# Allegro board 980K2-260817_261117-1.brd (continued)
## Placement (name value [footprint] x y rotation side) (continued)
NOREF#1107  -  []  178.97 271.91 90 top
NOREF#1108  -  []  211.21 294.89 90 top
NOREF#1109  -  []  279.22 250.88 90 top
NOREF#1110  -  []  256.83 227.03 0 top
NOREF#1111  -  []  271.19 228.49 0 top
NOREF#1112  -  []  171.05 289.49 0 top
NOREF#1113  -  []  237.92 250.01 0 top
NOREF#1114  -  []  158.11 172.1 0 top
NOREF#1115  -  []  226.16 272.17 90 top
NOREF#1116  -  []  244.44 232.28 90 top
NOREF#1117  -  []  214.38 264.09 0 top
NOREF#1118  -  []  93.68 156.59 0 top
NOREF#1119  -  []  149.84 224.11 0 top
NOREF#1120  -  []  262.87 273.02 0 top
NOREF#1121  -  []  149.72 221.62 0 top
NOREF#1122  -  []  144.16 256.43 90 top
NOREF#1123  -  []  275.17 272.17 0 top
NOREF#1124  -  []  146.16 193.35 0 top
NOREF#1125  -  []  224.16 251.6 90 top
NOREF#1126  -  []  273.94 256.75 0 top
NOREF#1127  -  []  277.74 166.36 90 top
NOREF#1128  -  []  214.43 232.23 0 top
NOREF#1129  -  []  208.54 267.5 90 top
NOREF#1130  -  []  196.61 233.37 90 top
NOREF#1131  -  []  283.84 270.87 90 top
NOREF#1132  -  []  135.82 266.44 0 top
NOREF#1133  -  []  218.83 292.23 0 top
NOREF#1134  -  []  119.48 396.29 0 top
NOREF#1135  -  []  237.74 226.35 90 top
NOREF#1136  -  []  273.27 198.18 0 top
NOREF#1137  -  []  152.46 247.68 90 top
NOREF#1138  -  []  243.97 270.55 90 top
NOREF#1139  -  []  148.35 223.79 90 top
NOREF#1140  -  []  262.03 229.03 90 top
NOREF#1141  -  []  157.5 245.31 90 top
NOREF#1142  -  []  193.6 216.55 0 top
NOREF#1143  -  []  193.39 193.03 90 top
NOREF#1144  -  []  236.33 167.9 90 top
NOREF#1145  -  []  269.84 279.54 90 top
NOREF#1146  -  []  248.54 202.09 0 top
NOREF#1147  -  []  186.01 250.88 90 top
NOREF#1148  -  []  163.84 264.78 90 top
NOREF#1149  -  []  272.13 284.66 0 top
NOREF#1150  -  []  276.7 257.85 90 top
NOREF#1151  -  []  159.27 210.87 90 top
NOREF#1152  -  []  89.76 164.74 90 top
NOREF#1153  -  []  239.4 213.09 90 top
NOREF#1154  -  []  129.49 266.31 0 top
NOREF#1155  -  []  279.27 205.58 0 top
NOREF#1156  -  []  185.42 214.72 90 top
NOREF#1157  -  []  147.77 248.11 90 top
NOREF#1158  -  []  237.71 233.69 0 top
NOREF#1159  -  []  211.25 244.35 0 top
NOREF#1160  -  []  279.27 268.62 0 top
NOREF#1161  -  []  135.15 263.21 0 top
NOREF#1162  -  []  225.41 286.99 90 top
NOREF#1163  -  []  187.01 458.49 0 top
NOREF#1164  -  []  157.71 173.69 90 top
NOREF#1165  -  []  277.71 233.69 0 top
NOREF#1166  -  []  243.97 274.54 0 top
NOREF#1167  -  []  164.95 267.27 90 top
NOREF#1168  -  []  195.05 278.82 0 top
NOREF#1169  -  []  162.57 291.95 0 top
NOREF#1170  -  []  239.4 274.54 0 top
NOREF#1171  -  []  206.32 209.17 0 top
NOREF#1172  -  []  203.84 214.21 0 top
NOREF#1173  -  []  150.88 168.6 90 top
NOREF#1174  -  []  233.27 198.18 0 top
NOREF#1175  -  []  171.25 244.35 0 top
NOREF#1176  -  []  240.23 176.17 90 top
NOREF#1177  -  []  0 382.27 0 top
NOREF#1178  -  []  189.12 251.6 90 top
NOREF#1179  -  []  203.97 208.95 0 top
NOREF#1180  -  []  266.43 222.5 90 top
NOREF#1181  -  []  243.4 296.38 0 top
NOREF#1182  -  []  266.28 253.03 90 top
NOREF#1183  -  []  141.43 285.38 90 top
NOREF#1184  -  []  236.7 257.85 90 top
NOREF#1185  -  []  230.97 190.88 90 top
NOREF#1186  -  []  228.32 242.05 0 top
NOREF#1187  -  []  279.4 262.09 0 top
NOREF#1188  -  []  274.39 282.02 90 top
NOREF#1189  -  []  137.28 272.5 90 top
NOREF#1190  -  []  156.02 247.68 0 top
NOREF#1191  -  []  190.97 190.88 90 top
NOREF#1192  -  []  289.52 207.27 90 top
NOREF#1193  -  []  256.98 265.11 90 top
NOREF#1194  -  []  317.15 392.33 90 top
NOREF#1195  -  []  232.13 280.09 0 top
NOREF#1196  -  []  230.77 279.22 90 top
NOREF#1197  -  []  119.46 18.69 90 top
NOREF#1198  -  []  138.95 264.09 0 top
NOREF#1199  -  []  256.63 232.23 0 top
NOREF#1200  -  []  237.37 191.6 90 top
NOREF#1201  -  []  231.19 283.92 0 top
NOREF#1202  -  []  235.05 218.82 0 top
NOREF#1203  -  []  187.43 284.11 0 top
NOREF#1204  -  []  215.02 208.14 90 top
NOREF#1205  -  []  225 456.29 0 top
NOREF#1206  -  []  239.4 204.45 90 top
NOREF#1207  -  []  212.87 227.4 90 top
NOREF#1208  -  []  140.83 265.79 90 top
NOREF#1209  -  []  271.91 256.43 90 top
NOREF#1210  -  []  152.66 226.35 90 top
NOREF#1211  -  []  197.03 178.07 0 top
NOREF#1212  -  []  193.18 211.85 90 top
NOREF#1213  -  []  168.42 261.77 0 top
NOREF#1214  -  []  243.84 214.21 0 top
NOREF#1215  -  []  249.05 232.28 0 top
NOREF#1216  -  []  203.84 205.58 0 top
NOREF#1217  -  []  266.01 184.91 90 top
NOREF#1218  -  []  283.84 271.67 0 top
NOREF#1219  -  []  156.02 192.78 0 top
NOREF#1220  -  []  230.56 197.6 0 top
NOREF#1221  -  []  220.43 284.38 90 top
NOREF#1222  -  []  122.57 231.95 0 top
NOREF#1223  -  []  236.54 227 0 top
NOREF#1224  -  []  275.15 236.17 90 top
NOREF#1225  -  []  210.92 291.95 90 top
NOREF#1226  -  []  203.97 272 0 top
NOREF#1227  -  []  148.32 245.63 0 top
NOREF#1228  -  []  189.84 224.11 0 top
NOREF#1229  -  []  270.56 197.6 0 top
NOREF#1230  -  []  204.64 241.15 90 top
NOREF#1231  -  []  147.03 171.4 0 top
NOREF#1232  -  []  220.83 201.22 90 top
NOREF#1233  -  []  273.27 253.35 0 top
NOREF#1234  -  []  228.32 253.35 0 top
NOREF#1235  -  []  248.54 207.5 90 top
NOREF#1236  -  []  186.16 286.14 90 top
NOREF#1237  -  []  239.27 261.77 0 top
NOREF#1238  -  []  159.27 271.67 0 top
NOREF#1239  -  []  147.77 181.47 0 top
NOREF#1240  -  []  208.94 281.73 0 top
NOREF#1241  -  []  267.05 269.24 0 top
NOREF#1242  -  []  206.32 202.32 0 top
NOREF#1243  -  []  204.95 210.32 90 top
NOREF#1244  -  []  229.12 256.43 90 top
NOREF#1245  -  []  212.55 190.49 90 top
NOREF#1246  -  []  266.43 282.49 90 top
NOREF#1247  -  []  249.52 200.42 90 top
NOREF#1248  -  []  180.95 266.12 90 top
NOREF#1249  -  []  169.52 270.32 90 top
NOREF#1250  -  []  277.5 185.31 90 top
NOREF#1251  -  []  276.57 185.63 0 top
NOREF#1252  -  []  152.13 280.09 0 top
NOREF#1253  -  []  273.27 258.18 0 top
NOREF#1254  -  []  154.33 267.37 90 top
NOREF#1255  -  []  245.38 286.23 0 top
NOREF#1256  -  []  276.57 193.35 0 top
NOREF#1257  -  []  145.42 286.99 90 top
NOREF#1258  -  []  286.32 212.22 0 top
NOREF#1259  -  []  275.49 168.7 90 top
NOREF#1260  -  []  178.83 292.23 0 top
NOREF#1261  -  []  293.99 17.15 0 top
NOREF#1262  -  []  153.39 257.85 90 top
NOREF#1263  -  []  188.95 206.89 0 top
NOREF#1264  -  []  279.27 267.82 90 top
NOREF#1265  -  []  176.72 18.69 0 top
NOREF#1266  -  []  267.3 226.19 0 top
NOREF#1267  -  []  239.24 244.35 0 top
NOREF#1268  -  []  199.4 214.54 0 top
NOREF#1269  -  []  236.52 225.69 0 top
NOREF#1270  -  []  223.49 197.85 90 top
NOREF#1271  -  []  181.85 232.5 0 top
NOREF#1272  -  []  267.43 278.27 90 top
NOREF#1273  -  []  161.75 272.22 0 top
NOREF#1274  -  []  277.04 244.35 0 top
NOREF#1275  -  []  231.79 251.93 0 top
NOREF#1276  -  []  147.43 218.27 0 top
NOREF#1277  -  []  154.63 283.79 90 top
NOREF#1278  -  []  226.43 282.49 90 top
NOREF#1279  -  []  271.79 191.93 0 top
NOREF#1280  -  []  187.43 278.27 0 top
NOREF#1281  -  []  241.75 266.13 0 top
NOREF#1282  -  []  148.95 206.89 0 top
NOREF#1283  -  []  213.45 184.35 0 top
NOREF#1284  -  []  256.55 280.49 0 top
NOREF#1285  -  []  144.71 252.5 90 top
NOREF#1286  -  []  272.25 272.17 0 top
NOREF#1287  -  []  201.75 209.17 0 top
NOREF#1288  -  []  230.6 233.69 0 top
NOREF#1289  -  []  242.85 297.22 0 top
NOREF#1290  -  []  208.54 205.9 0 top
NOREF#1291  -  []  203.84 260.97 90 top
NOREF#1292  -  []  258.35 211.84 0 top
NOREF#1293  -  []  278.11 232.1 0 top
NOREF#1294  -  []  218.85 181.15 90 top
NOREF#1295  -  []  232.25 212.18 0 top
NOREF#1296  -  []  143.36 258.18 0 top
NOREF#1297  -  []  199.72 283.79 90 top
NOREF#1298  -  []  187 83.81 0 top
NOREF#1299  -  []  232.13 224.66 0 top
NOREF#1300  -  []  324.88 21.69 90 top
NOREF#1301  -  []  231.11 253.35 0 top
NOREF#1302  -  []  203.84 271.67 0 top
NOREF#1303  -  []  275.05 278.82 0 top
NOREF#1304  -  []  140.83 208.59 90 top
NOREF#1305  -  []  163.84 204.78 90 top
NOREF#1306  -  []  263.49 253.03 90 top
NOREF#1307  -  []  151.19 218.07 0 top
NOREF#1308  -  []  225.09 197.49 90 top
NOREF#1309  -  []  228.78 222.65 0 top
NOREF#1310  -  []  139.73 178.35 0 top
NOREF#1311  -  []  230.77 213.37 90 top
NOREF#1312  -  []  152.25 278.02 90 top
NOREF#1313  -  []  208.54 265.9 0 top
NOREF#1314  -  []  229.72 221.62 0 top
NOREF#1315  -  []  144.04 245.96 0 top
NOREF#1316  -  []  283.84 213.41 90 top
NOREF#1317  -  []  214.04 210.63 90 top
NOREF#1318  -  []  250.89 269.17 0 top
NOREF#1319  -  []  277.59 175.77 0 top
NOREF#1320  -  []  220.63 392.33 90 top
NOREF#1321  -  []  255.84 262.57 90 top
NOREF#1322  -  []  154.07 256.43 90 top
NOREF#1323  -  []  179.08 263.76 0 top
NOREF#1324  -  []  218.95 201.55 0 top
NOREF#1325  -  []  190.41 168.7 90 top
NOREF#1326  -  []  248.54 262.09 0 top
NOREF#1327  -  []  273.83 232.21 90 top
NOREF#1328  -  []  268.99 256.75 0 top
NOREF#1329  -  []  191.11 198.18 0 top
NOREF#1330  -  []  276.45 187.71 0 top
NOREF#1331  -  []  157.92 247.68 90 top
NOREF#1332  -  []  185.09 197.49 90 top
NOREF#1333  -  []  268.32 182.05 0 top
NOREF#1334  -  []  171.05 229.49 0 top
NOREF#1335  -  []  258.35 267.01 0 top
NOREF#1336  -  []  128.48 456.29 0 top
NOREF#1337  -  []  203.97 204.45 90 top
NOREF#1338  -  []  235.17 276.75 0 top
NOREF#1339  -  []  279.27 265.58 0 top
NOREF#1340  -  []  279.65 272.56 0 top
NOREF#1341  -  []  149.84 273.7 0 top
NOREF#1342  -  []  196.8 225.06 90 top
NOREF#1343  -  []  226.83 191.93 0 top
NOREF#1344  -  []  233.6 276.55 0 top
NOREF#1345  -  []  129.49 220.89 0 top
NOREF#1346  -  []  187.99 238.35 0 top
NOREF#1347  -  []  221.85 306.46 0 top
NOREF#1348  -  []  186.16 272.17 90 top
NOREF#1349  -  []  294.09 204.23 90 top
NOREF#1350  -  []  186.01 190.88 90 top
NOREF#1351  -  []  244.95 264.23 90 top
NOREF#1352  -  []  196.02 252.78 0 top
NOREF#1353  -  []  193.95 256.75 0 top
NOREF#1354  -  []  147.77 192.78 0 top
NOREF#1355  -  []  204.61 294.89 90 top
NOREF#1356  -  []  95.33 20.69 90 top
NOREF#1357  -  []  148.99 251.93 0 top
NOREF#1358  -  []  145.42 214.72 90 top
NOREF#1359  -  []  176.83 227.03 0 top
NOREF#1360  -  []  191.73 232.54 0 top
NOREF#1361  -  []  187.3 220.35 0 top
NOREF#1362  -  []  187.43 224.11 0 top
NOREF#1363  -  []  267.43 284.11 90 top
NOREF#1364  -  []  93.68 136.27 0 top
NOREF#1365  -  []  155.17 212.18 90 top
NOREF#1366  -  []  138.97 271.91 90 top
NOREF#1367  -  []  229.12 251.6 90 top
NOREF#1368  -  []  248.54 260.64 90 top
NOREF#1369  -  []  199.27 260.97 90 top
NOREF#1370  -  []  276.84 227.33 0 top
NOREF#1371  -  []  245.04 293.3 90 top
NOREF#1372  -  []  240.13 396.29 0 top
NOREF#1373  -  []  283.97 208.95 0 top
NOREF#1374  -  []  193.18 184.35 0 top
NOREF#1375  -  []  186.83 196.75 0 top
NOREF#1376  -  []  239.27 270.87 90 top
NOREF#1377  -  []  135.02 208.14 90 top
NOREF#1378  -  []  274.39 226.59 90 top
NOREF#1379  -  []  187.99 178.35 0 top
NOREF#1380  -  []  181.85 292.49 0 top
NOREF#1381  -  []  235.68 233.69 90 top
NOREF#1382  -  []  273.94 251.93 0 top
NOREF#1383  -  []  193.39 257.85 90 top
NOREF#1384  -  []  186.83 191.93 0 top
NOREF#1385  -  []  146.96 251.6 90 top
NOREF#1386  -  []  236.57 185.63 0 top
NOREF#1387  -  []  183.36 253.35 0 top
NOREF#1388  -  []  204.95 200.42 90 top
NOREF#1389  -  []  239.27 207.82 90 top
NOREF#1390  -  []  191.24 197.85 90 top
NOREF#1391  -  []  283.84 208.62 0 top
NOREF#1392  -  []  212.55 250.49 90 top
NOREF#1393  -  []  231.11 193.35 0 top
NOREF#1394  -  []  157.5 185.31 90 top
NOREF#1395  -  []  135.11 261.22 90 top
NOREF#1396  -  []  190.98 184.35 0 top
NOREF#1397  -  []  155.17 281.32 0 top
NOREF#1398  -  []  157.71 233.69 90 top
NOREF#1399  -  []  192.13 220.09 0 top
NOREF#1400  -  []  233.39 257.85 90 top
NOREF#1401  -  []  267.99 178.35 0 top
NOREF#1402  -  []  209.52 272.86 90 top
NOREF#1403  -  []  186.7 283.04 90 top
NOREF#1404  -  []  289.52 200.42 90 top
NOREF#1405  -  []  178.35 271.84 0 top
NOREF#1406  -  []  254.38 204.09 0 top
NOREF#1407  -  []  233.18 271.85 90 top
NOREF#1408  -  []  140.83 205.79 90 top
NOREF#1409  -  []  226.01 250.88 90 top
NOREF#1410  -  []  197.5 185.31 90 top
NOREF#1411  -  []  225.42 274.72 90 top
NOREF#1412  -  []  123.92 289.94 0 top
NOREF#1413  -  []  273.18 222.26 90 top
NOREF#1414  -  []  151.19 228.49 0 top
NOREF#1415  -  []  236.1 280.99 90 top
NOREF#1416  -  []  139.73 178.35 0 top
NOREF#1417  -  []  272.51 235.77 0 top
NOREF#1418  -  []  151.11 200.17 90 top
NOREF#1419  -  []  251.25 184.35 0 top
NOREF#1420  -  []  157.92 190.01 0 top
NOREF#1421  -  []  155.17 221.32 90 top
NOREF#1422  -  []  148.35 283.79 90 top
NOREF#1423  -  []  248.42 207.82 90 top
NOREF#1424  -  []  169.52 260.42 90 top
NOREF#1425  -  []  266.16 258.18 0 top
NOREF#1426  -  []  159.22 190.88 90 top
NOREF#1427  -  []  151.18 179.15 0 top
NOREF#1428  -  []  185.09 257.49 90 top
NOREF#1429  -  []  192.11 231.4 0 top
NOREF#1430  -  []  124.61 294.89 90 top
NOREF#1431  -  []  273.18 277.69 90 top
NOREF#1432  -  []  262.81 252.78 0 top
NOREF#1433  -  []  164.95 204.23 90 top
NOREF#1434  -  []  203.97 212 0 top
NOREF#1435  -  []  133.1 237.5 0 top
NOREF#1436  -  []  227.8 205.39 90 top
NOREF#1437  -  []  140.95 206.12 90 top
NOREF#1438  -  []  216 456.29 90 top
NOREF#1439  -  []  114.62 458.49 0 top
NOREF#1440  -  []  187.45 269.24 0 top
NOREF#1441  -  []  198.11 172.1 0 top
NOREF#1442  -  []  236.02 257.6 0 top
NOREF#1443  -  []  231.98 286.59 90 top
NOREF#1444  -  []  288.54 262.09 0 top
NOREF#1445  -  []  152.51 235.77 0 top
NOREF#1446  -  []  140.95 201.55 90 top
NOREF#1447  -  []  232.51 175.77 0 top
NOREF#1448  -  []  230.56 257.6 0 top
NOREF#1449  -  []  143.49 257.85 90 top
NOREF#1450  -  []  169.05 232.28 0 top
NOREF#1451  -  []  152.63 173.69 90 top
NOREF#1452  -  []  148.99 240.62 0 top
NOREF#1453  -  []  276.33 227.9 90 top
NOREF#1454  -  []  139.08 205.79 0 top
NOREF#1455  -  []  239.4 200.64 90 top
NOREF#1456  -  []  149.72 275.77 0 top
NOREF#1457  -  []  166.32 269.17 0 top
NOREF#1458  -  []  254.43 292.23 0 top
NOREF#1459  -  []  188.78 184.35 0 top
NOREF#1460  -  []  268.95 206.89 0 top
NOREF#1461  -  []  226.01 184.91 90 top
NOREF#1462  -  []  276.84 167.33 0 top
NOREF#1463  -  []  236.1 211.85 90 top
NOREF#1464  -  []  163.84 265.58 0 top
NOREF#1465  -  []  242.44 292.28 0 top
NOREF#1466  -  []  227.45 209.24 0 top
NOREF#1467  -  []  213.36 201.22 0 top
NOREF#1468  -  []  259.73 178.35 0 top
NOREF#1469  -  []  125.04 233.3 90 top
NOREF#1470  -  []  143.49 247.06 90 top
NOREF#1471  -  []  151.98 220.75 90 top
NOREF#1472  -  []  288.42 200.97 90 top
NOREF#1473  -  []  277.92 250.01 0 top
NOREF#1474  -  []  180.95 264.09 90 top
NOREF#1475  -  []  269.55 248.99 90 top
NOREF#1476  -  []  222.81 197.6 0 top
NOREF#1477  -  []  173.45 244.35 0 top
NOREF#1478  -  []  279.4 202.09 0 top
NOREF#1479  -  []  193.6 276.55 0 top
NOREF#1480  -  []  239.22 239.57 90 top
NOREF#1481  -  []  281.75 262.32 0 top
NOREF#1482  -  []  268.81 255.7 90 top
NOREF#1483  -  []  211.05 289.49 0 top
NOREF#1484  -  []  229.12 180.3 90 top
NOREF#1485  -  []  262.81 192.78 0 top
NOREF#1486  -  []  228.78 184.35 0 top
NOREF#1487  -  []  157.37 196.43 90 top
NOREF#1488  -  []  161.41 227.9 90 top
NOREF#1489  -  []  255.84 202.57 90 top
NOREF#1490  -  []  197.71 232.86 0 top
NOREF#1491  -  []  223.36 247.38 0 top
NOREF#1492  -  []  276.1 220.99 90 top
NOREF#1493  -  []  235.05 223.39 0 top
NOREF#1494  -  []  143.49 253.03 90 top
NOREF#1495  -  []  145.42 273.02 90 top
NOREF#1496  -  []  156.79 171.3 0 top
NOREF#1497  -  []  288.42 204.78 90 top
NOREF#1498  -  []  214.07 210.89 90 top
NOREF#1499  -  []  246.32 274.76 0 top
NOREF#1500  -  []  188.44 253.03 90 top
NOREF#1501  -  []  183.49 247.06 90 top
NOREF#1502  -  []  264.26 456.29 90 top
NOREF#1503  -  []  157.28 264.37 0 top
NOREF#1504  -  []  276.8 285.06 90 top
NOREF#1505  -  []  156.57 198.18 0 top
NOREF#1506  -  []  271.46 227 0 top
NOREF#1507  -  []  151.19 223.92 0 top
NOREF#1508  -  []  275.49 228.7 90 top
NOREF#1509  -  []  230.97 255.7 90 top
NOREF#1510  -  []  270.48 175.77 0 top
NOREF#1511  -  []  164.04 237.5 90 top
NOREF#1512  -  []  225.61 257.6 0 top
NOREF#1513  -  []  169.05 292.28 0 top
NOREF#1514  -  []  155.17 276.75 0 top
NOREF#1515  -  []  244.61 234.24 90 top
NOREF#1516  -  []  203.84 264.78 90 top
NOREF#1517  -  []  191.53 233.37 90 top
NOREF#1518  -  []  214.09 207.27 90 top
NOREF#1519  -  []  209.52 270.32 90 top
NOREF#1520  -  []  172.64 264.47 0 top
NOREF#1521  -  []  268.78 244.35 0 top
NOREF#1522  -  []  182.81 192.78 0 top
NOREF#1523  -  []  263.36 258.18 0 top
NOREF#1524  -  []  195.17 212.18 90 top
NOREF#1525  -  []  192.72 252.78 0 top
NOREF#1526  -  []  95.35 456.29 90 top
NOREF#1527  -  []  190.56 257.6 0 top
NOREF#1528  -  []  163.84 200.97 90 top
NOREF#1529  -  []  239.4 207.5 90 top
NOREF#1530  -  []  260.83 201.22 90 top
NOREF#1531  -  []  272.51 175.77 0 top
NOREF#1532  -  []  159.06 238.07 0 top
NOREF#1533  -  []  231.24 197.85 90 top
NOREF#1534  -  []  277.92 190.01 0 top
NOREF#1535  -  []  117.23 452.29 90 top
NOREF#1536  -  []  163.97 272 0 top
NOREF#1537  -  []  132.64 204.47 0 top
NOREF#1538  -  []  283.84 267.82 90 top
NOREF#1539  -  []  228.44 253.03 90 top
NOREF#1540  -  []  272.72 197.6 0 top
NOREF#1541  -  []  196.79 231.3 0 top
NOREF#1542  -  []  277.37 191.6 90 top
NOREF#1543  -  []  225.09 257.49 90 top
NOREF#1544  -  []  318.12 17.15 90 top
NOREF#1545  -  []  227.3 220.35 0 top
NOREF#1546  -  []  231.19 228.49 0 top
NOREF#1547  -  []  180.83 261.22 90 top
NOREF#1548  -  []  197.74 166.36 90 top
NOREF#1549  -  []  139.08 208.59 0 top
NOREF#1550  -  []  156.7 181.72 90 top
NOREF#1551  -  []  158.04 228.3 0 top
NOREF#1552  -  []  147.8 204.99 90 top
NOREF#1553  -  []  269.86 17.15 0 top
NOREF#1554  -  []  268.32 185.63 90 top
NOREF#1555  -  []  233.18 217.69 90 top
NOREF#1556  -  []  272.25 222.59 90 top
NOREF#1557  -  []  265.41 273.02 90 top
NOREF#1558  -  []  209.17 231.95 0 top
NOREF#1559  -  []  272.25 278.02 90 top
NOREF#1560  -  []  131.22 234.24 90 top
NOREF#1561  -  []  272.66 166.36 90 top
NOREF#1562  -  []  118.64 291.4 0 top
NOREF#1563  -  []  177.29 187.78 0 top
NOREF#1564  -  []  210.89 269.17 0 top
NOREF#1565  -  []  189.55 248.99 90 top
NOREF#1566  -  []  239.22 255.7 90 top
NOREF#1567  -  []  289.52 212.86 90 top
NOREF#1568  -  []  266.01 244.91 90 top
NOREF#1569  -  []  266.96 256.43 90 top
NOREF#1570  -  []  146.88 283.95 0 top
NOREF#1571  -  []  194.78 176.5 90 top
NOREF#1572  -  []  263.36 198.18 0 top
NOREF#1573  -  []  149.84 279.54 0 top
NOREF#1574  -  []  171.22 234.24 90 top
NOREF#1575  -  []  205.04 293.3 90 top
NOREF#1576  -  []  239.22 190.88 90 top
NOREF#1577  -  []  158.91 172.21 90 top
NOREF#1578  -  []  152.25 282.59 90 top
NOREF#1579  -  []  260.59 184.98 90 top
NOREF#1580  -  []  153.76 190.88 90 top
NOREF#1581  -  []  217.25 176.5 90 top
NOREF#1582  -  []  221.03 267.69 90 top
NOREF#1583  -  []  279.4 265.9 0 top
NOREF#1584  -  []  85.84 137.3 0 top
NOREF#1585  -  []  281.75 206.13 0 top
NOREF#1586  -  []  239.27 214.21 0 top
NOREF#1587  -  []  254.07 270.89 90 top
NOREF#1588  -  []  163.92 229.94 0 top
NOREF#1589  -  []  228.99 196.75 0 top
NOREF#1590  -  []  134.51 263.76 0 top
NOREF#1591  -  []  199.4 265.9 0 top
NOREF#1592  -  []  152.25 218.02 0 top
NOREF#1593  -  []  209.52 267.27 90 top
NOREF#1594  -  []  190.77 219.22 90 top
NOREF#1595  -  []  142.03 229.03 90 top
NOREF#1596  -  []  271.19 223.92 0 top
NOREF#1597  -  []  154.39 226.59 90 top
NOREF#1598  -  []  148.44 241.72 90 top
NOREF#1599  -  []  281.12 248.11 90 top
NOREF#1600  -  []  239.27 205.58 0 top
NOREF#1601  -  []  190.56 197.6 0 top
NOREF#1602  -  []  227.77 241.47 0 top
NOREF#1603  -  []  163.97 262.09 0 top
NOREF#1604  -  []  147.43 284.11 0 top
NOREF#1605  -  []  192.63 232.86 0 top
NOREF#1606  -  []  155.15 236.17 90 top
NOREF#1607  -  []  256.63 292.23 0 top
NOREF#1608  -  []  254.43 232.23 0 top
NOREF#1609  -  []  259.08 208.59 0 top
NOREF#1610  -  []  199.4 262.09 0 top
NOREF#1611  -  []  246.32 214.76 0 top
NOREF#1612  -  []  164.95 207.27 90 top
NOREF#1613  -  []  188.78 288.49 0 top
NOREF#1614  -  []  196.1 220.99 90 top
NOREF#1615  -  []  251.36 18.69 90 top
NOREF#1616  -  []  125.25 291.4 90 top
NOREF#1617  -  []  197.37 256.43 90 top
NOREF#1618  -  []  251.05 185.49 90 top
NOREF#1619  -  []  144.04 251.93 0 top
NOREF#1620  -  []  153.27 193.35 0 top
NOREF#1621  -  []  244.61 294.89 90 top
NOREF#1622  -  []  243.97 267.5 90 top
NOREF#1623  -  []  235.17 221.32 90 top
NOREF#1624  -  []  131.22 234.89 90 top
NOREF#1625  -  []  191.79 256.75 0 top
NOREF#1626  -  []  89.74 135.6 0 top
NOREF#1627  -  []  268.32 245.63 90 top
NOREF#1628  -  []  279.27 271.67 0 top
NOREF#1629  -  []  228.78 184.35 0 top
NOREF#1630  -  []  211.25 244.35 0 top
NOREF#1631  -  []  236.02 241.47 0 top
NOREF#1632  -  []  203.84 208.62 0 top
NOREF#1633  -  []  195.17 281.32 90 top
NOREF#1634  -  []  260.95 206.12 90 top
NOREF#1635  -  []  188.19 187.71 0 top
NOREF#1636  -  []  236.38 241.15 90 top
NOREF#1637  -  []  269.24 185.31 90 top
NOREF#1638  -  []  185.41 286.99 90 top
NOREF#1639  -  []  253.45 184.35 0 top
NOREF#1640  -  []  266.16 260.17 90 top
NOREF#1641  -  []  186.16 200.17 90 top
NOREF#1642  -  []  273.18 217.69 90 top
NOREF#1643  -  []  271.73 232.54 0 top
NOREF#1644  -  []  187.8 204.99 90 top
NOREF#1645  -  []  138.95 261.55 0 top
NOREF#1646  -  []  152.87 188.11 90 top
NOREF#1647  -  []  133.24 261.55 0 top
NOREF#1648  -  []  230.97 195.7 90 top
NOREF#1649  -  []  156.81 232.54 0 top
NOREF#1650  -  []  164.64 181.15 90 top
NOREF#1651  -  []  193.98 178.07 0 top
NOREF#1652  -  []  143.36 198.18 0 top
NOREF#1653  -  []  185.61 192.78 0 top
NOREF#1654  -  []  236.61 173.37 90 top
NOREF#1655  -  []  193.6 226.96 0 top
NOREF#1656  -  []  195.96 228.6 90 top
NOREF#1657  -  []  236.57 193.35 0 top
NOREF#1658  -  []  151.79 251.93 0 top
NOREF#1659  -  []  269.72 215.77 0 top
NOREF#1660  -  []  236.8 280.49 90 top
NOREF#1661  -  []  260.83 263.76 90 top
NOREF#1662  -  []  277.04 184.35 0 top
NOREF#1663  -  []  214.09 267.27 90 top
NOREF#1664  -  []  196.57 185.63 0 top
NOREF#1665  -  []  173.78 207.01 0 top
NOREF#1666  -  []  221.55 265.11 90 top
NOREF#1667  -  []  267.77 197.6 0 top
NOREF#1668  -  []  184.16 256.43 90 top
NOREF#1669  -  []  275.05 214.25 0 top
NOREF#1670  -  []  154.33 264.33 90 top
NOREF#1671  -  []  188.32 242.05 0 top
NOREF#1672  -  []  218.35 271.84 0 top
NOREF#1673  -  []  183.36 198.18 0 top
NOREF#1674  -  []  106.68 148.34 0 top
NOREF#1675  -  []  138.95 201.55 0 top
NOREF#1676  -  []  210.89 206.13 0 top
NOREF#1677  -  []  255.24 261.55 90 top
NOREF#1678  -  []  192.63 173.69 90 top
NOREF#1679  -  []  225.41 273.02 90 top
NOREF#1680  -  []  267.45 209.24 0 top
NOREF#1681  -  []  180.95 268.91 90 top
NOREF#1682  -  []  183.36 193.35 0 top
NOREF#1683  -  []  288.42 201.77 0 top
NOREF#1684  -  []  239.72 219.22 90 top
NOREF#1685  -  []  276.45 247.71 0 top
NOREF#1686  -  []  136.55 254.49 90 top
NOREF#1687  -  []  260.95 201.55 90 top
NOREF#1688  -  []  83.04 164.54 90 top
NOREF#1689  -  []  276.52 216.55 0 top
NOREF#1690  -  []  142.81 197.6 0 top
NOREF#1691  -  []  180.95 208.91 90 top
NOREF#1692  -  []  276.02 257.6 0 top
NOREF#1693  -  []  242.26 176.17 90 top
NOREF#1694  -  []  188.19 247.71 0 top
NOREF#1695  -  []  199.27 267.82 90 top
NOREF#1696  -  []  180.43 224.38 90 top
NOREF#1697  -  []  174.09 200.42 90 top
NOREF#1698  -  []  268.81 190.88 90 top
NOREF#1699  -  []  157.8 14.59 90 top
NOREF#1700  -  []  217.25 236.5 90 top
NOREF#1701  -  []  203.84 204.78 90 top
NOREF#1702  -  []  191.19 278.07 0 top
NOREF#1703  -  []  250.92 291.95 90 top
NOREF#1704  -  []  250.92 231.95 90 top
NOREF#1705  -  []  236.57 245.63 90 top
NOREF#1706  -  []  157.03 238.07 0 top
NOREF#1707  -  []  234.39 216.17 90 top
NOREF#1708  -  []  169.52 264.23 90 top
NOREF#1709  -  []  226.01 190.88 90 top
NOREF#1710  -  []  201.75 262.32 0 top
NOREF#1711  -  []  139.08 263.76 0 top
NOREF#1712  -  []  270.77 283.79 90 top
NOREF#1713  -  []  245.73 17.15 0 top
NOREF#1714  -  []  156.57 185.63 90 top
NOREF#1715  -  []  143.49 187.06 90 top
NOREF#1716  -  []  163.92 289.94 0 top
NOREF#1717  -  []  215.84 262.57 90 top
NOREF#1718  -  []  254.38 264.09 0 top
NOREF#1719  -  []  142.81 252.5 0 top
NOREF#1720  -  []  277.71 173.69 90 top
NOREF#1721  -  []  288.54 265.9 0 top
NOREF#1722  -  []  148.44 253.03 90 top
NOREF#1723  -  []  233.56 173.37 90 top
NOREF#1724  -  []  211.05 245.49 90 top
NOREF#1725  -  []  284.95 267.27 90 top
NOREF#1726  -  []  178.95 204.09 0 top
NOREF#1727  -  []  276.57 258.18 0 top
NOREF#1728  -  []  159.4 208.95 0 top
NOREF#1729  -  []  192.51 175.77 0 top
NOREF#1730  -  []  289.52 204.23 90 top
NOREF#1731  -  []  222.81 252.78 0 top
NOREF#1732  -  []  164.95 260.42 90 top
NOREF#1733  -  []  173.62 289.09 90 top
NOREF#1734  -  []  147.43 224.11 0 top
NOREF#1735  -  []  138.83 232.23 0 top
NOREF#1736  -  []  199.22 239.57 90 top
NOREF#1737  -  []  228.32 193.35 0 top
NOREF#1738  -  []  171.05 185.49 90 top
NOREF#1739  -  []  246.32 202.32 0 top
NOREF#1740  -  []  190.97 195.7 90 top
NOREF#1741  -  []  268.19 247.71 0 top
NOREF#1742  -  []  288.42 205.58 0 top
NOREF#1743  -  []  279.27 270.87 90 top
NOREF#1744  -  []  216.38 264.09 90 top
NOREF#1745  -  []  151.7 288.26 0 top
NOREF#1746  -  []  288.54 268.95 0 top
NOREF#1747  -  []  196.7 193.03 90 top
NOREF#1748  -  []  135.43 276.18 0 top
NOREF#1749  -  []  203.84 210.87 90 top
NOREF#1750  -  []  149.29 285.22 0 top
NOREF#1751  -  []  161.44 244.35 0 top
NOREF#1752  -  []  261.55 205.11 90 top
NOREF#1753  -  []  237.25 251.93 0 top
NOREF#1754  -  []  230.77 273.37 90 top
NOREF#1755  -  []  209.49 280.89 0 top
NOREF#1756  -  []  203.4 236.38 0 top
NOREF#1757  -  []  184.16 251.6 90 top
NOREF#1758  -  []  179.08 205.79 0 top
NOREF#1759  -  []  136.38 264.09 90 top
NOREF#1760  -  []  187.77 241.47 0 top
NOREF#1761  -  []  290.89 269.17 0 top
NOREF#1762  -  []  283.97 213.09 90 top
NOREF#1763  -  []  190.15 266.89 90 top
NOREF#1764  -  []  272.63 233.69 90 top
NOREF#1765  -  []  168.42 264.78 90 top
NOREF#1766  -  []  178.95 264.09 0 top
NOREF#1767  -  []  261.55 267.14 90 top
NOREF#1768  -  []  226.7 283.04 90 top
NOREF#1769  -  []  203.97 214.54 0 top
NOREF#1770  -  []  245.04 233.3 90 top
NOREF#1771  -  []  263.36 193.35 0 top
NOREF#1772  -  []  203.97 262.09 0 top
NOREF#1773  -  []  204.95 204.23 90 top
NOREF#1774  -  []  243.84 264.78 90 top
NOREF#1775  -  []  228.78 244.35 0 top
NOREF#1776  -  []  142.88 226.99 0 top
NOREF#1777  -  []  106.58 18.69 90 top
NOREF#1778  -  []  267.8 209.99 0 top
NOREF#1779  -  []  227.43 218.27 0 top
NOREF#1780  -  []  178.35 211.84 0 top
NOREF#1781  -  []  268.99 251.93 0 top
NOREF#1782  -  []  174.43 292.23 0 top
NOREF#1783  -  []  168.94 281.73 0 top
NOREF#1784  -  []  232.72 197.6 0 top
NOREF#1785  -  []  266.16 272.17 90 top
NOREF#1786  -  []  220.83 268.59 90 top
NOREF#1787  -  []  218.35 209.04 0 top
NOREF#1788  -  []  219.72 213.6 90 top
NOREF#1789  -  []  142.81 192.78 0 top
NOREF#1790  -  []  235.56 235.77 0 top
NOREF#1791  -  []  159.27 200.97 90 top
NOREF#1792  -  []  206.32 262.32 0 top
NOREF#1793  -  []  148.44 197.85 90 top
NOREF#1794  -  []  277.25 240.62 0 top
NOREF#1795  -  []  147.43 278.27 0 top
NOREF#1796  -  []  192.72 192.78 0 top
NOREF#1797  -  []  215.24 261.55 90 top
NOREF#1798  -  []  271.71 171.3 0 top
NOREF#1799  -  []  138.74 83.81 0 top
NOREF#1800  -  []  236.84 167.33 0 top
NOREF#1801  -  []  196.8 274.65 90 top
NOREF#1802  -  []  222.81 192.78 0 top
NOREF#1803  -  []  151.73 172.54 0 top
NOREF#1804  -  []  253.24 201.55 0 top
NOREF#1805  -  []  139.72 273.6 90 top
NOREF#1806  -  []  95.35 456.29 0 top
NOREF#1807  -  []  191.19 228.49 0 top
NOREF#1808  -  []  279.65 212.56 0 top
NOREF#1809  -  []  172.55 190.49 90 top
NOREF#1810  -  []  205.38 226.23 0 top
NOREF#1811  -  []  188.44 241.72 90 top
NOREF#1812  -  []  219.08 268.59 0 top
NOREF#1813  -  []  106.68 148.34 90 top
NOREF#1814  -  []  258.95 268.91 0 top
NOREF#1815  -  []  192.13 280.09 0 top
NOREF#1816  -  []  62.86 375.04 0 top
NOREF#1817  -  []  182.87 273.02 0 top
NOREF#1818  -  []  230.6 173.69 90 top
NOREF#1819  -  []  254.51 263.76 0 top
NOREF#1820  -  []  155.17 221.32 0 top
NOREF#1821  -  []  127.04 239.09 0 top
NOREF#1822  -  []  135.15 265.24 0 top
NOREF#1823  -  []  235.56 175.77 0 top
NOREF#1824  -  []  141.55 202.57 90 top
NOREF#1825  -  []  231.11 198.18 0 top
NOREF#1826  -  []  247.98 286.38 90 top
NOREF#1827  -  []  180.83 263.76 90 top
NOREF#1828  -  []  156.45 187.71 0 top
NOREF#1829  -  []  187.8 205.39 90 top
NOREF#1830  -  []  227.9 205.84 90 top
NOREF#1831  -  []  241.12 188.11 90 top
NOREF#1832  -  []  220.95 208.91 90 top
NOREF#1833  -  []  199.72 214.65 90 top
NOREF#1834  -  []  218.95 268.91 0 top
NOREF#1835  -  []  201.41 227.9 90 top
NOREF#1836  -  []  252.64 264.47 0 top
NOREF#1837  -  []  190.97 250.88 90 top
NOREF#1838  -  []  283.84 211.67 0 top
NOREF#1839  -  []  181.55 265.11 90 top
NOREF#1840  -  []  203.97 274.54 0 top
NOREF#1841  -  []  195.68 173.69 90 top
NOREF#1842  -  []  279.4 210.55 90 top
NOREF#1843  -  []  159.4 274.54 0 top
NOREF#1844  -  []  199.72 223.79 90 top
NOREF#1845  -  []  216.83 227.03 0 top
NOREF#1846  -  []  169.49 220.89 0 top
NOREF#1847  -  []  283.84 260.97 90 top
NOREF#1848  -  []  233.18 282.26 90 top
NOREF#1849  -  []  151.79 256.75 0 top
NOREF#1850  -  []  156.45 247.71 0 top
NOREF#1851  -  []  224.16 196.43 90 top
NOREF#1852  -  []  266.16 193.35 0 top
NOREF#1853  -  []  133.62 289.09 90 top
NOREF#1854  -  []  249.49 280.89 0 top
NOREF#1855  -  []  258.85 241.15 90 top
NOREF#1856  -  []  231.53 173.37 90 top
NOREF#1857  -  []  134.07 210.89 90 top
NOREF#1858  -  []  273.18 271.85 90 top
NOREF#1859  -  []  244.61 294.24 90 top
NOREF#1860  -  []  226.16 198.18 0 top
NOREF#1861  -  []  213.75 452.29 90 top
NOREF#1862  -  []  159.4 213.09 90 top
NOREF#1863  -  []  275.05 218.82 0 top
NOREF#1864  -  []  173.78 267.01 0 top
NOREF#1865  -  []  148.19 187.71 0 top
NOREF#1866  -  []  176.63 232.23 0 top
NOREF#1867  -  []  220.95 261.55 90 top
NOREF#1868  -  []  180.83 203.76 90 top
NOREF#1869  -  []  268.32 193.35 0 top
NOREF#1870  -  []  150.21 82.65 0 top
NOREF#1871  -  []  156.1 211.85 90 top
NOREF#1872  -  []  209.87 389.27 90 top
NOREF#1873  -  []  204.95 272.86 90 top
NOREF#1874  -  []  263.49 197.85 90 top
NOREF#1875  -  []  195.58 262.67 90 top
NOREF#1876  -  []  191.24 253.03 90 top
NOREF#1877  -  []  233.94 251.93 0 top
NOREF#1878  -  []  86.61 132.84 0 top
NOREF#1879  -  []  164.61 234.24 90 top
NOREF#1880  -  []  245.38 286.23 0 top
NOREF#1881  -  []  164.95 200.42 90 top
NOREF#1882  -  []  283.53 457.2 0 top
NOREF#1883  -  []  153.18 277.69 90 top
NOREF#1884  -  []  321.52 456.29 0 top
NOREF#1885  -  []  228.32 185.63 90 top
NOREF#1886  -  []  189.12 256.43 90 top
NOREF#1887  -  []  273.76 190.88 90 top
NOREF#1888  -  []  199.4 210.55 90 top
NOREF#1889  -  []  180.83 205.79 90 top
NOREF#1890  -  []  202.26 176.17 90 top
NOREF#1891  -  []  151.79 191.93 0 top
NOREF#1892  -  []  189.84 219.54 90 top
NOREF#1893  -  []  239.27 265.58 0 top
NOREF#1894  -  []  159.4 210.55 90 top
NOREF#1895  -  []  226.28 257.85 90 top
NOREF#1896  -  []  155.05 278.82 0 top
NOREF#1897  -  []  221.59 308.11 0 top
NOREF#1898  -  []  131.26 184.35 0 top
NOREF#1899  -  []  258.83 292.23 0 top
NOREF#1900  -  []  182.03 289.03 90 top
NOREF#1901  -  []  119.48 456.29 0 top
NOREF#1902  -  []  229.67 250.01 0 top
NOREF#1903  -  []  216.55 280.49 0 top
NOREF#1904  -  []  225.61 197.6 0 top
NOREF#1905  -  []  279.24 244.35 0 top
NOREF#1906  -  []  199.4 212 0 top
NOREF#1907  -  []  209.55 237.49 0 top
NOREF#1908  -  []  289.52 270.32 90 top
NOREF#1909  -  []  176.26 203.76 90 top
NOREF#1910  -  []  149.21 17.15 90 top
NOREF#1911  -  []  176.83 287.03 0 top
NOREF#1912  -  []  267.8 269.99 0 top
NOREF#1913  -  []  206.32 272.22 0 top
NOREF#1914  -  []  217.29 187.78 0 top
NOREF#1915  -  []  275.92 255.7 90 top
NOREF#1916  -  []  195.92 255.7 90 top
NOREF#1917  -  []  268.19 187.71 0 top
NOREF#1918  -  []  237.71 233.69 90 top
NOREF#1919  -  []  147.43 278.27 90 top
NOREF#1920  -  []  228.44 181.72 90 top
NOREF#1921  -  []  219.08 261.22 0 top
NOREF#1922  -  []  196.8 220.49 90 top
NOREF#1923  -  []  154.63 282.42 0 top
NOREF#1924  -  []  234.39 276.17 90 top
NOREF#1925  -  []  155.17 276.75 90 top
NOREF#1926  -  []  143.61 456.29 0 top
NOREF#1927  -  []  178.35 209.04 0 top
NOREF#1928  -  []  276.7 197.85 90 top
NOREF#1929  -  []  150.6 173.69 0 top
NOREF#1930  -  []  135.66 184.35 0 top
NOREF#1931  -  []  270.77 219.22 90 top
NOREF#1932  -  []  150.48 175.77 0 top
NOREF#1933  -  []  220.95 204.09 90 top
NOREF#1934  -  []  193.76 195.7 90 top
NOREF#1935  -  []  165.38 286.23 0 top
NOREF#1936  -  []  196.81 172.54 0 top
NOREF#1937  -  []  137.29 187.78 0 top
NOREF#1938  -  []  236.52 276.55 0 top
NOREF#1939  -  []  153.18 184.35 0 top
NOREF#1940  -  []  192.11 171.4 0 top
NOREF#1941  -  []  199.27 201.77 0 top
NOREF#1942  -  []  276.33 167.9 90 top
NOREF#1943  -  []  159.27 270.87 90 top
NOREF#1944  -  []  152.11 231.4 0 top
NOREF#1945  -  []  196.7 257.85 90 top
NOREF#1946  -  []  248.42 200.97 90 top
NOREF#1947  -  []  262.87 286.99 0 top
NOREF#1948  -  []  209.55 237.49 90 top
NOREF#1949  -  []  133.24 201.55 0 top
NOREF#1950  -  []  233.98 238.07 0 top
NOREF#1951  -  []  273.03 172.1 0 top
NOREF#1952  -  []  149.56 259.27 90 top
NOREF#1953  -  []  211.65 233.3 90 top
NOREF#1954  -  []  214.09 204.23 90 top
NOREF#1955  -  []  272.13 214.25 0 top
NOREF#1956  -  []  239.44 239.15 0 top
NOREF#1957  -  []  138.95 266.12 0 top
NOREF#1958  -  []  167.04 299.09 0 top
NOREF#1959  -  []  275.17 216.75 90 top
NOREF#1960  -  []  211.21 234.89 90 top
NOREF#1961  -  []  247.04 239.09 0 top
NOREF#1962  -  []  229.67 190.01 0 top
NOREF#1963  -  []  153.39 253.03 90 top
NOREF#1964  -  []  226.01 255.7 90 top
NOREF#1965  -  []  148.44 257.85 90 top
NOREF#1966  -  []  192.13 224.66 0 top
NOREF#1967  -  []  191.11 200.17 90 top
NOREF#1968  -  []  274.33 204.33 90 top
NOREF#1969  -  []  199.27 208.62 0 top
NOREF#1970  -  []  272.72 192.78 0 top
NOREF#1971  -  []  195.17 212.18 0 top
NOREF#1972  -  []  277.71 232.86 0 top
NOREF#1973  -  []  205.74 14.59 90 top
NOREF#1974  -  []  283.97 265.9 0 top
NOREF#1975  -  []  267.8 205.39 90 top
NOREF#1976  -  []  276.57 245.63 0 top
NOREF#1977  -  []  293.02 392.33 90 top
NOREF#1978  -  []  193.83 172.21 90 top
NOREF#1979  -  []  288.54 204.45 90 top
NOREF#1980  -  []  151.7 277.85 0 top
NOREF#1981  -  []  104.35 456.29 0 top
NOREF#1982  -  []  183.49 257.85 90 top
NOREF#1983  -  []  271.11 258.18 0 top
NOREF#1984  -  []  270.56 192.78 0 top
NOREF#1985  -  []  196.57 253.35 0 top
NOREF#1986  -  []  185.61 252.78 0 top
NOREF#1987  -  []  230.77 223.79 90 top
NOREF#1988  -  []  226.83 256.75 0 top
NOREF#1989  -  []  243.97 200.64 90 top
NOREF#1990  -  []  237.18 236.17 90 top
NOREF#1991  -  []  164.95 210.32 90 top
NOREF#1992  -  []  258.97 271.91 90 top
NOREF#1993  -  []  152.13 284.66 0 top
NOREF#1994  -  []  241.84 235.2 0 top
NOREF#1995  -  []  201.12 188.11 90 top
NOREF#1996  -  []  142.03 289.03 90 top
NOREF#1997  -  []  229.84 219.54 0 top
NOREF#1998  -  []  147.05 209.24 0 top
NOREF#1999  -  []  160.23 176.17 90 top
NOREF#2000  -  []  216 396.29 0 top
NOREF#2001  -  []  235.92 190.88 90 top
NOREF#2002  -  []  136.26 263.76 90 top
NOREF#2003  -  []  150.48 235.77 0 top
NOREF#2004  -  []  233.98 178.07 0 top
NOREF#2005  -  []  243.84 268.62 0 top
NOREF#2006  -  []  197.47 17.15 90 top
NOREF#2007  -  []  255.65 244.35 0 top
NOREF#2008  -  []  149.29 286.59 90 top
NOREF#2009  -  []  275.17 221.32 0 top
NOREF#2010  -  []  268.78 184.35 0 top
NOREF#2011  -  []  159.27 267.82 90 top
NOREF#2012  -  []  199.27 204.78 90 top
NOREF#2013  -  []  175.24 201.55 90 top
NOREF#2014  -  []  214.51 203.76 0 top
NOREF#2015  -  []  267.43 224.11 90 top
NOREF#2016  -  []  271.91 251.6 90 top
NOREF#2017  -  []  159.27 204.78 90 top
NOREF#2018  -  []  265.61 192.78 0 top
NOREF#2019  -  []  276.52 225.69 0 top
NOREF#2020  -  []  271.24 257.85 90 top
NOREF#2021  -  []  276.52 285.69 0 top
NOREF#2022  -  []  236.7 241.72 90 top
NOREF#2023  -  []  167.04 239.09 0 top
NOREF#2024  -  []  140.95 204.09 90 top
NOREF#2025  -  []  233.83 232.21 90 top
NOREF#2026  -  []  153.18 222.26 90 top
NOREF#2027  -  []  156.81 172.54 0 top
NOREF#2028  -  []  273.98 238.07 0 top
NOREF#2029  -  []  156.1 271.85 90 top
NOREF#2030  -  []  271.18 239.15 0 top
NOREF#2031  -  []  183.89 245.24 90 top
NOREF#2032  -  []  228.99 240.62 0 top
NOREF#2033  -  []  135.84 202.57 90 top
NOREF#2034  -  []  235.49 168.7 90 top
NOREF#2035  -  []  234.07 191.6 90 top
NOREF#2036  -  []  253.65 239.15 0 top
NOREF#2037  -  []  193.18 282.26 90 top
NOREF#2038  -  []  275.58 202.67 90 top
NOREF#2039  -  []  205.04 233.3 90 top
NOREF#2040  -  []  229.84 284.11 0 top
NOREF#2041  -  []  147.9 265.84 90 top
NOREF#2042  -  []  312.52 396.29 0 top
NOREF#2043  -  []  242.26 236.17 90 top
NOREF#2044  -  []  267.77 241.47 0 top
NOREF#2045  -  []  180.95 261.55 90 top
NOREF#2046  -  []  244.95 260.42 90 top
NOREF#2047  -  []  239.72 279.22 90 top
NOREF#2048  -  []  279.27 260.97 90 top
NOREF#2049  -  []  229.24 185.31 90 top
NOREF#2050  -  []  159.22 179.57 90 top
NOREF#2051  -  []  152.25 212.18 90 top
NOREF#2052  -  []  155.68 173.69 90 top
NOREF#2053  -  []  137.25 176.5 90 top
NOREF#2054  -  []  235.58 262.67 90 top
NOREF#2055  -  []  215.59 16.49 0 top
NOREF#2056  -  []  229.84 279.54 90 top
NOREF#2057  -  []  181.03 207.69 90 top
NOREF#2058  -  []  190.48 175.77 0 top
NOREF#2059  -  []  220.95 268.91 90 top
NOREF#2060  -  []  208.42 207.82 90 top
NOREF#2061  -  []  189.72 221.62 0 top
NOREF#2062  -  []  201.12 248.11 90 top
NOREF#2063  -  []  268.78 288.49 0 top
NOREF#2064  -  []  146.88 289.79 0 top
NOREF#2065  -  []  237.59 175.77 0 top
NOREF#2066  -  []  152.63 232.86 0 top
NOREF#2067  -  []  236.61 233.37 90 top
NOREF#2068  -  []  139.55 180.49 90 top
NOREF#2069  -  []  248.54 265.9 0 top
NOREF#2070  -  []  143.36 193.35 0 top
NOREF#2071  -  []  144.16 185.63 90 top
NOREF#2072  -  []  263.49 247.06 90 top
NOREF#2073  -  []  203.84 213.41 90 top
NOREF#2074  -  []  154.07 196.43 90 top
NOREF#2075  -  []  267.77 252.78 0 top
NOREF#2076  -  []  199.24 244.35 0 top
NOREF#2077  -  []  213.64 239.09 0 top
NOREF#2078  -  []  276.02 181.47 0 top
NOREF#2079  -  []  182.81 186.81 0 top
NOREF#2080  -  []  156.54 227 0 top
NOREF#2081  -  []  157.59 175.77 0 top
NOREF#2082  -  []  163.97 260.64 90 top
NOREF#2083  -  []  157.03 178.07 0 top
NOREF#2084  -  []  227.03 171.4 0 top
NOREF#2085  -  []  287.25 19.69 90 top
NOREF#2086  -  []  191.87 396.29 0 top
NOREF#2087  -  []  208.54 268.95 0 top
NOREF#2088  -  []  271.18 179.15 0 top
NOREF#2089  -  []  271.79 196.75 0 top
NOREF#2090  -  []  222.03 229.03 90 top
NOREF#2091  -  []  151.46 167 0 top
NOREF#2092  -  []  179.08 265.79 0 top
NOREF#2093  -  []  233.18 222.26 90 top
NOREF#2094  -  []  239.27 208.62 0 top
NOREF#2095  -  []  254 14.59 90 top
NOREF#2096  -  []  181.22 76.69 90 top
NOREF#2097  -  []  196.57 182.05 0 top
NOREF#2098  -  []  128.46 18.69 0 top
NOREF#2099  -  []  268.32 242.05 0 top
NOREF#2100  -  []  231.19 278.07 0 top
NOREF#2101  -  []  249.52 212.86 90 top
NOREF#2102  -  []  196.7 197.85 90 top
NOREF#2103  -  []  244.32 291.95 90 top
NOREF#2104  -  []  307.66 457.2 0 top
NOREF#2105  -  []  226.96 256.43 90 top
NOREF#2106  -  []  208.54 208.95 0 top
NOREF#2107  -  []  203.84 211.67 0 top
NOREF#2108  -  []  150.56 247.68 0 top
NOREF#2109  -  []  248.45 235.2 0 top
NOREF#2110  -  []  130.58 263.21 0 top
NOREF#2111  -  []  156.02 197.6 0 top
NOREF#2112  -  []  235.92 255.7 90 top
NOREF#2113  -  []  189.72 275.77 0 top
NOREF#2114  -  []  190.6 233.69 90 top
NOREF#2115  -  []  272.13 220.09 0 top
NOREF#2116  -  []  187.43 284.11 90 top
NOREF#2117  -  []  258.85 181.15 90 top
NOREF#2118  -  []  283.84 204.78 90 top
NOREF#2119  -  []  221.55 267.14 90 top
NOREF#2120  -  []  286.32 266.13 0 top
NOREF#2121  -  []  134.38 264.09 0 top
NOREF#2122  -  []  136.5 271.94 90 top
NOREF#2123  -  []  281.75 202.32 0 top
NOREF#2124  -  []  263.89 185.24 90 top
NOREF#2125  -  []  138.56 246.51 0 top
NOREF#2126  -  []  235.17 281.32 0 top
NOREF#2127  -  []  275.17 276.75 90 top
NOREF#2128  -  []  153.98 178.07 0 top
NOREF#2129  -  []  162.57 231.95 0 top
NOREF#2130  -  []  183.49 193.03 90 top
NOREF#2131  -  []  153.6 216.55 0 top
NOREF#2132  -  []  124.61 234.24 90 top
NOREF#2133  -  []  243.97 208.95 0 top
NOREF#2134  -  []  114.55 316.49 0 top
NOREF#2135  -  []  157.74 226.35 90 top
NOREF#2136  -  []  190.77 273.37 90 top
NOREF#2137  -  []  152.25 222.59 0 top
NOREF#2138  -  []  208.42 261.77 0 top
NOREF#2139  -  []  230.41 228.7 90 top
NOREF#2140  -  []  221.6 17.15 90 top
NOREF#2141  -  []  243.84 201.77 0 top
NOREF#2142  -  []  273.6 286.96 0 top
NOREF#2143  -  []  269.12 251.6 90 top
NOREF#2144  -  []  237.25 180.62 0 top
NOREF#2145  -  []  141.55 209.94 90 top
NOREF#2146  -  []  261.55 207.14 90 top
NOREF#2147  -  []  148.44 181.72 90 top
NOREF#2148  -  []  146.01 184.91 90 top
NOREF#2149  -  []  164.61 234.89 90 top
NOREF#2150  -  []  227.43 218.27 90 top
NOREF#2151  -  []  203.97 264.45 90 top
NOREF#2152  -  []  95.35 452.29 90 top
NOREF#2153  -  []  144.04 191.93 0 top
NOREF#2154  -  []  266.43 236.47 90 top
NOREF#2155  -  []  220.95 201.55 90 top
NOREF#2156  -  []  270.6 233.69 0 top
NOREF#2157  -  []  157.25 251.93 0 top
NOREF#2158  -  []  199.4 270.55 90 top
NOREF#2159  -  []  267.03 171.4 0 top
NOREF#2160  -  []  186.43 222.5 90 top
NOREF#2161  -  []  186.01 195.7 90 top
NOREF#2162  -  []  153.95 196.75 0 top
NOREF#2163  -  []  195.49 168.7 90 top
NOREF#2164  -  []  225.61 192.78 0 top
NOREF#2165  -  []  273.83 172.21 90 top
NOREF#2166  -  []  204.95 212.86 90 top
NOREF#2167  -  []  236.54 167 0 top
NOREF#2168  -  []  194.39 276.17 90 top
NOREF#2169  -  []  89.76 165.64 0 top
NOREF#2170  -  []  198.91 172.21 90 top
NOREF#2171  -  []  253.62 289.09 90 top
NOREF#2172  -  []  269.84 219.54 0 top
NOREF#2173  -  []  212.87 287.4 90 top
NOREF#2174  -  []  155.17 272.17 0 top
NOREF#2175  -  []  211.21 294.24 90 top
NOREF#2176  -  []  182.87 226.99 0 top
NOREF#2177  -  []  323.77 454.29 90 top
NOREF#2178  -  []  288.54 207.5 90 top
NOREF#2179  -  []  258.35 207.01 0 top
NOREF#2180  -  []  275.17 281.32 0 top
NOREF#2181  -  []  258.83 232.23 0 top
NOREF#2182  -  []  258.95 264.09 0 top
NOREF#2183  -  []  119.48 456.29 90 top
NOREF#2184  -  []  251.21 294.24 90 top
NOREF#2185  -  []  239.27 260.97 90 top
NOREF#2186  -  []  127.98 226.38 90 top
NOREF#2187  -  []  226.96 191.6 90 top
NOREF#2188  -  []  147.77 252.5 0 top
NOREF#2189  -  []  166.32 274.76 0 top
NOREF#2190  -  []  230.15 266.89 90 top
NOREF#2191  -  []  288.39 452.29 90 top
NOREF#2192  -  []  237.92 190.01 0 top
NOREF#2193  -  []  232.66 166.36 90 top
NOREF#2194  -  []  186.96 196.43 90 top
NOREF#2195  -  []  269.24 245.31 90 top
NOREF#2196  -  []  191.46 167 0 top
NOREF#2197  -  []  230.6 173.69 0 top
NOREF#2198  -  []  193.27 193.35 0 top
NOREF#2199  -  []  218.95 261.55 0 top
NOREF#2200  -  []  213.24 261.55 0 top
NOREF#2201  -  []  157.18 236.17 90 top
NOREF#2202  -  []  275.17 281.32 90 top
NOREF#2203  -  []  150.15 266.89 90 top
NOREF#2204  -  []  134.38 204.09 0 top
NOREF#2205  -  []  199.65 272.56 0 top
NOREF#2206  -  []  275.68 173.69 0 top
NOREF#2207  -  []  209.55 237.49 90 top
NOREF#2208  -  []  138.85 241.15 90 top
NOREF#2209  -  []  268.44 197.85 90 top
NOREF#2210  -  []  279.22 179.57 90 top
NOREF#2211  -  []  274.39 286.59 90 top
NOREF#2212  -  []  89.74 155.92 90 top
NOREF#2213  -  []  276.02 252.78 0 top
NOREF#2214  -  []  161.84 295.2 0 top
NOREF#2215  -  []  159.4 268.95 0 top
NOREF#2216  -  []  232.25 282.59 0 top
NOREF#2217  -  []  175.24 261.55 90 top
NOREF#2218  -  []  215.65 184.35 0 top
NOREF#2219  -  []  163.97 270.55 90 top
NOREF#2220  -  []  239.72 223.79 90 top
NOREF#2221  -  []  231.98 220.75 90 top
NOREF#2222  -  []  206.32 274.76 0 top
NOREF#2223  -  []  255.24 201.55 90 top
NOREF#2224  -  []  136.26 203.76 90 top
NOREF#2225  -  []  162.87 16.49 0 top
NOREF#2226  -  []  279.4 260.64 90 top
NOREF#2227  -  []  262.81 257.6 0 top
NOREF#2228  -  []  190.97 179.57 90 top
NOREF#2229  -  []  148.99 256.75 0 top
NOREF#2230  -  []  208.54 264.45 90 top
NOREF#2231  -  []  261.59 294.14 0 top
NOREF#2232  -  []  196.57 193.35 0 top
NOREF#2233  -  []  197.04 244.35 0 top
NOREF#2234  -  []  188.32 185.63 0 top
NOREF#2235  -  []  193.18 277.69 90 top
NOREF#2236  -  []  149.84 213.7 0 top
NOREF#2237  -  []  192.63 173.69 0 top
NOREF#2238  -  []  269.84 224.11 90 top
NOREF#2239  -  []  221.59 248.12 0 top
NOREF#2240  -  []  147.77 247.68 0 top
NOREF#2241  -  []  169.52 204.23 90 top
NOREF#2242  -  []  204.95 264.23 90 top
NOREF#2243  -  []  239.4 210.55 90 top
NOREF#2244  -  []  145.61 197.6 0 top
NOREF#2245  -  []  191.91 256.43 90 top
NOREF#2246  -  []  166.32 262.32 0 top
NOREF#2247  -  []  231.98 280.75 90 top
NOREF#2248  -  []  257.25 176.5 90 top
NOREF#2249  -  []  264.16 256.43 90 top
NOREF#2250  -  []  80.49 155.57 0 top
NOREF#2251  -  []  188.32 245.63 90 top
NOREF#2252  -  []  163.84 201.77 0 top
NOREF#2253  -  []  148.78 228.49 0 top
NOREF#2254  -  []  191.87 456.29 90 top
NOREF#2255  -  []  148.32 185.63 90 top
NOREF#2256  -  []  175.65 184.35 0 top
NOREF#2257  -  []  235.17 216.75 0 top
NOREF#2258  -  []  277.74 226.35 90 top
NOREF#2259  -  []  279.22 255.7 90 top
NOREF#2260  -  []  152.13 224.66 0 top
NOREF#2261  -  []  227.43 224.11 0 top
NOREF#2262  -  []  268.81 195.7 90 top
NOREF#2263  -  []  186.28 253.03 90 top
NOREF#2264  -  []  244.95 212.86 90 top
NOREF#2265  -  []  219.08 265.79 0 top
NOREF#2266  -  []  213.78 267.01 0 top
NOREF#2267  -  []  199.27 214.21 0 top
NOREF#2268  -  []  210.89 262.32 0 top
NOREF#2269  -  []  228.99 180.62 0 top
NOREF#2270  -  []  239.72 283.79 90 top
NOREF#2271  -  []  242.85 237.22 0 top
NOREF#2272  -  []  213.62 289.09 90 top
NOREF#2273  -  []  203.97 268.95 0 top
NOREF#2274  -  []  246.32 272.22 0 top
NOREF#2275  -  []  243.84 207.82 90 top
NOREF#2276  -  []  202.2 238.35 0 top
NOREF#2277  -  []  233.94 191.93 0 top
NOREF#2278  -  []  159.4 200.64 90 top
NOREF#2279  -  []  233.76 190.88 90 top
NOREF#2280  -  []  214.04 270.63 90 top
NOREF#2281  -  []  231.71 231.3 0 top
NOREF#2282  -  []  202.44 292.28 0 top
NOREF#2283  -  []  83.04 144.22 90 top
NOREF#2284  -  []  273.39 197.85 90 top
NOREF#2285  -  []  229.55 248.99 90 top
NOREF#2286  -  []  192.87 248.11 90 top
NOREF#2287  -  []  58.41 375.29 0 top
NOREF#2288  -  []  269.84 279.54 0 top
NOREF#2289  -  []  277.03 178.07 0 top
NOREF#2290  -  []  164.32 231.95 90 top
NOREF#2291  -  []  265.41 213.02 90 top
NOREF#2292  -  []  168.42 260.97 90 top
NOREF#2293  -  []  138.95 204.09 0 top
NOREF#2294  -  []  195.92 190.88 90 top
NOREF#2295  -  []  231.18 239.15 0 top
NOREF#2296  -  []  159.4 264.45 90 top
NOREF#2297  -  []  268.35 277.95 90 top
NOREF#2298  -  []  201.84 295.2 0 top
NOREF#2299  -  []  236.02 181.47 0 top
NOREF#2300  -  []  232.72 252.78 0 top
NOREF#2301  -  []  224.04 191.93 0 top
NOREF#2302  -  []  197.37 180.3 90 top
NOREF#2303  -  []  278.13 389.27 90 top
NOREF#2304  -  []  201.75 206.13 0 top
NOREF#2305  -  []  163.84 205.58 0 top
NOREF#2306  -  []  259.08 203.76 0 top
NOREF#2307  -  []  153.18 271.85 90 top
NOREF#2308  -  []  144.16 245.63 90 top
NOREF#2309  -  []  157.37 251.6 90 top
NOREF#2310  -  []  241.75 269.17 0 top
NOREF#2311  -  []  231.46 227 0 top
NOREF#2312  -  []  250.89 262.32 0 top
NOREF#2313  -  []  124.44 232.28 90 top
NOREF#2314  -  []  197.37 196.43 90 top
NOREF#2315  -  []  156.54 167 0 top
NOREF#2316  -  []  163.97 264.45 90 top
NOREF#2317  -  []  202.57 231.95 0 top
NOREF#2318  -  []  192.87 188.11 90 top
NOREF#2319  -  []  179.08 261.22 0 top
NOREF#2320  -  []  248.42 205.58 0 top
NOREF#2321  -  []  197.25 251.93 0 top
NOREF#2322  -  []  163.97 273.09 90 top
NOREF#2323  -  []  269.12 191.6 90 top
NOREF#2324  -  []  234.33 207.37 90 top
NOREF#2325  -  []  187.43 218.27 90 top
NOREF#2326  -  []  228.95 266.89 0 top
NOREF#2327  -  []  294.09 207.27 90 top
NOREF#2328  -  []  184.04 256.75 0 top
NOREF#2329  -  []  267.9 265.84 90 top
NOREF#2330  -  []  150.97 195.7 90 top
NOREF#2331  -  []  235.58 202.67 90 top
NOREF#2332  -  []  222.81 186.81 0 top
NOREF#2333  -  []  232.25 272.17 0 top
NOREF#2334  -  []  182.81 252.78 0 top
NOREF#2335  -  []  227.8 209.99 0 top
NOREF#2336  -  []  235.17 272.17 90 top
NOREF#2337  -  []  227.99 178.35 0 top
NOREF#2338  -  []  216.38 204.09 90 top
NOREF#2339  -  []  147.3 286.19 0 top
NOREF#2340  -  []  271.53 173.37 90 top
NOREF#2341  -  []  191.19 283.92 0 top
NOREF#2342  -  []  202.2 238.35 0 top
NOREF#2343  -  []  236.8 225.06 90 top
NOREF#2344  -  []  196.1 211.85 90 top
NOREF#2345  -  []  260.95 268.91 90 top
NOREF#2346  -  []  149.55 156.49 90 top
NOREF#2347  -  []  271.73 172.54 0 top
NOREF#2348  -  []  187.99 238.35 0 top
NOREF#2349  -  []  187.05 269.24 0 top
NOREF#2350  -  []  187.77 197.6 0 top
NOREF#2351  -  []  192.25 218.02 0 top
NOREF#2352  -  []  207.98 286.38 90 top
NOREF#2353  -  []  283.97 260.64 90 top
NOREF#2354  -  []  222.81 257.6 0 top
NOREF#2355  -  []  226.16 286.14 90 top
NOREF#2356  -  []  254.51 203.76 0 top
NOREF#2357  -  []  312.5 18.69 90 top
NOREF#2358  -  []  146.88 286.59 90 top
NOREF#2359  -  []  133.36 261.22 0 top
NOREF#2360  -  []  199.4 273.09 90 top
NOREF#2361  -  []  209.55 237.49 90 top
NOREF#2362  -  []  145.09 197.49 90 top
NOREF#2363  -  []  135.24 201.55 90 top
NOREF#2364  -  []  220.83 263.76 90 top
NOREF#2365  -  []  171.22 294.89 90 top
NOREF#2366  -  []  163.97 274.54 0 top
NOREF#2367  -  []  214.07 270.89 90 top
NOREF#2368  -  []  249.52 264.23 90 top
NOREF#2369  -  []  172.55 250.49 90 top
NOREF#2370  -  []  109.54 14.59 90 top
NOREF#2371  -  []  276.02 241.47 0 top
NOREF#2372  -  []  239.06 178.07 0 top
NOREF#2373  -  []  219.08 203.76 0 top
NOREF#2374  -  []  222.87 213.02 0 top
NOREF#2375  -  []  268.95 266.89 0 top
NOREF#2376  -  []  235.17 281.32 90 top
NOREF#2377  -  []  263.36 247.38 0 top
